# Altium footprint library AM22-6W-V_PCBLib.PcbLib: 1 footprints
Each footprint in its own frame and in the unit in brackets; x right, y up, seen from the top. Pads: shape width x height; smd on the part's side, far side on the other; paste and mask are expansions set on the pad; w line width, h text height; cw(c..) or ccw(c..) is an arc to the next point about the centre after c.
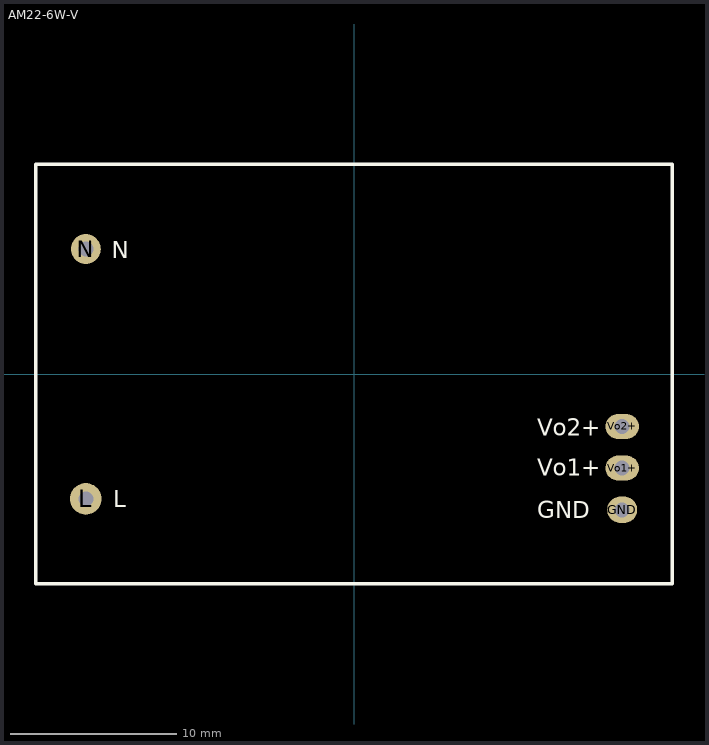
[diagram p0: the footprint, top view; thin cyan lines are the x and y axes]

## AM22-6W-V [mm]
pads (5):
  oval 1.8x1.6 hole 0.9: GND(16.1,-8.15)
  round 1.9 hole 0.9: L(-16.1,-7.5)
  round 1.8 hole 0.9: N(-16.1,7.5)
  oval 2x1.5 hole 0.9: Vo1+(16.1,-5.65) Vo2+(16.1,-3.15)
TopOverlay:
  lines w0.2: -19.1,-12.6 -19.1,12.6 19.1,12.6 19.1,-12.6 -19.1,-12.6
  text "N" at -14.55,6.95 h1
  text "L" at -14.45,-8 h1
  text "GND" at 11,-8.65 h1
  text "Vo1+" at 11,-6.1 h1
  text "Vo2+" at 11,-3.7 h1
